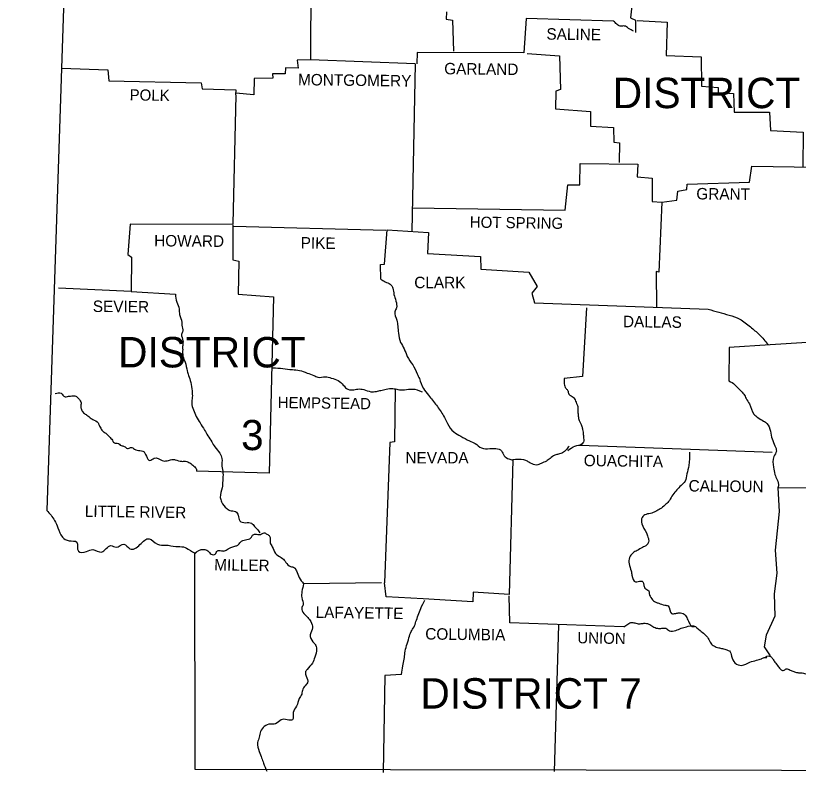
# Model space of a CAD drawing. Extents: x 21307 to 29830, y 1322443 to 1332359.
# Drawn here: x 25205.3 to 25498.6, y 1325967.3 to 1326251 of the extents above; entities that cross this region are included whole.
import ezdxf

# ---------------------------------------------------------------- set-up
doc = ezdxf.new("R2010")
doc.units = 0
doc.layers.add('R_Draft', color=7, linetype='Continuous')

msp = doc.modelspace()

# ---------------------------------------------------------------- linework, layer by layer
at = {"layer": 'R_Draft'}
msp.add_line((25354.96, 1326232.9), (25353.8, 1326170.1), dxfattribs=at)
for points in [[(25205.26, 1326503), (25225.96, 1326336.8), (25216.96, 1326065.5)], [(25370.26, 1326319.9), (25369.86, 1326305.5), (25347.06, 1326305.4), (25344.06, 1326302.8), (25342.36, 1326298.8), (25339.86, 1326299), (25339.76, 1326296.7), (25336.86, 1326296.4), (25336.96, 1326294.3), (25322.46, 1326294.7), (25321.96, 1326293.1), (25315.96, 1326292.9), (25315.76, 1326234.54)], [(25469.16, 1326264.2), (25461.96, 1326265), (25462.26, 1326262.3), (25449.16, 1326261.8), (25448.76, 1326257.9), (25436.46, 1326257.2), (25435.76, 1326250.2), (25437.56, 1326249.3), (25437.56, 1326244.7)], [(25366.76, 1326252.4), (25366.66, 1326249.7), (25368.96, 1326249.3), (25369.36, 1326237.7)], [(25429.36, 1326248.9), (25396.66, 1326249.9), (25395.76, 1326237), (25355.76, 1326237.2), (25355.6, 1326232.87)], [(25438.26, 1326249.2), (25449.46, 1326248.5), (25449.06, 1326236), (25462.16, 1326235.5), (25462.36, 1326224.6), (25468.56, 1326224.1), (25468.56, 1326222.2), (25474.36, 1326221.8), (25474.56, 1326214.8), (25487.76, 1326214.8), (25488.16, 1326207.9), (25500.36, 1326207.3), (25500.26, 1326194.3)], [(25396.96, 1326236.8), (25409.06, 1326235.9), (25409.46, 1326223.3), (25407.76, 1326222.7), (25407.56, 1326216), (25420.66, 1326215.1), (25420.66, 1326209.6), (25429.36, 1326209.1), (25429.46, 1326203.6), (25431.56, 1326203.3), (25431.46, 1326195.9)], [(25315.76, 1326234.54), (25315.76, 1326234.4), (25310.76, 1326234.3), (25311.16, 1326231.3), (25306.36, 1326231.4), (25306.26, 1326229.2), (25301.56, 1326229.2), (25301.66, 1326227.6), (25294.66, 1326227.4), (25294.56, 1326221.3), (25287.77, 1326221.9)], [(25354.96, 1326232.9), (25315.76, 1326234.4)], [(25222.46, 1326231.3), (25239.76, 1326230.7), (25240.16, 1326226.5), (25274.76, 1326225.8), (25275.16, 1326223.6), (25287.76, 1326223.2), (25287.66, 1326221.3)], [(25287.74, 1326221.12), (25286.66, 1326172.9)], [(25353.96, 1326178.9), (25411.16, 1326178.1), (25412.26, 1326187.6), (25416.76, 1326187.6), (25416.86, 1326195.6), (25438.46, 1326195.3), (25438.26, 1326190.5), (25443.86, 1326190.1), (25443.86, 1326181.3), (25447.46, 1326181), (25447.42, 1326180.08)], [(25447.46, 1326181), (25453.06, 1326181.8), (25453.46, 1326185.2), (25456.76, 1326185.8), (25456.96, 1326187.8), (25480.26, 1326188.5), (25481.16, 1326194.6), (25505.06, 1326194.2)], [(25447.46, 1326181), (25446.26, 1326154.8), (25445.36, 1326155.1), (25445.46, 1326141.5)], [(25286.56, 1326172.7), (25248.16, 1326172.8), (25247.26, 1326161.4), (25248.66, 1326160.4), (25248.56, 1326147.6), (25221.26, 1326148.8)], [(25286.66, 1326172.7), (25286.66, 1326159.4), (25288.86, 1326159), (25288.66, 1326146.6), (25301.86, 1326145.6), (25300.26, 1326079.5), (25273.06, 1326080.2)], [(25286.86, 1326172), (25344.06, 1326170.5)], [(25342.16, 1326152.2), (25341.96, 1326157.7), (25343.56, 1326157.8), (25344.56, 1326170.7), (25359.96, 1326169.7), (25359.56, 1326161.8), (25379.46, 1326160.7), (25379.56, 1326155.9), (25397.56, 1326154.8), (25400.66, 1326149.4), (25398.76, 1326147), (25399.66, 1326143.3), (25464.86, 1326140.9)], [(25248.56, 1326147.6), (25265.16, 1326146.6)], [(25419.26, 1326141.4), (25417.76, 1326115.7), (25410.86, 1326114.9)], [(25488.03, 1326127.55), (25472.66, 1326126.6), (25472.56, 1326114.1)], [(25501.86, 1326128.4), (25488.03, 1326127.55)], [(25347.46, 1326111.1), (25347.26, 1326091.2), (25345.46, 1326091), (25343.46, 1326038.3)], [(25416.76, 1326090), (25458.16, 1326088.5), (25488.86, 1326087.3)], [(25391.56, 1326084.4), (25390.26, 1326034), (25376.76, 1326034.9), (25376.66, 1326031.2), (25357.99, 1326032.29)], [(25490.86, 1326074), (25536.06, 1326074.1)], [(25490.86, 1326074), (25491.43, 1326065.09), (25489.96, 1326050.62), (25490.59, 1326042.01), (25489.54, 1326034.25), (25489.75, 1326025.85), (25486.6, 1326018.72), (25485.76, 1326014.31), (25488.07, 1326010.95)], [(25272.26, 1326049.4), (25272.46, 1325968.5), (25638.96, 1325967.9)], [(25342.34, 1326038.29), (25313.16, 1326038)], [(25357.99, 1326032.29), (25344.16, 1326033.1), (25343.46, 1326038.3)], [(25433.16, 1326021.8), (25390.46, 1326023.4), (25390.26, 1326033.5)], [(25408.66, 1326022.5), (25407.06, 1325967.6)], [(25349.86, 1326004), (25343.66, 1326003.6), (25342.96, 1325967.3)]]:
    msp.add_lwpolyline(points, dxfattribs=at)
for points in [[(25436.86, 1326245.2), (25434.96, 1326246.2), (25433.46, 1326247.1), (25431.86, 1326247), (25430.56, 1326247.8), (25429.36, 1326248.9)], [(25342.16, 1326152.2), (25343.76, 1326151.2), (25345.66, 1326150.3), (25346.66, 1326148.8), (25347.06, 1326146.5), (25347.76, 1326144), (25347.96, 1326141.4), (25347.36, 1326140), (25348.16, 1326136.8), (25348.46, 1326134.6), (25348.76, 1326132), (25349.56, 1326128.5), (25350.86, 1326126.1), (25352.06, 1326123.2), (25354.06, 1326120.1), (25355.76, 1326116.7), (25356.56, 1326114.9), (25358.06, 1326111.2), (25359.96, 1326108.7), (25362.96, 1326104.9), (25365.66, 1326101), (25367.16, 1326098.1), (25369.46, 1326094.9), (25372.06, 1326093.3), (25375.36, 1326091.6), (25377.46, 1326090.6), (25379.86, 1326088.9), (25382.96, 1326088.7), (25385.26, 1326088.7), (25387.36, 1326087.8), (25388.36, 1326086), (25390.16, 1326084.8), (25391.56, 1326084.4)], [(25265.16, 1326146.6), (25265.66, 1326143.6), (25266.56, 1326141), (25266.66, 1326139), (25267.56, 1326136), (25267.56, 1326134.9), (25267.86, 1326132.7), (25267.46, 1326131.5), (25267.96, 1326129.1), (25267.86, 1326127.3), (25267.86, 1326125.8), (25267.96, 1326123.3), (25268.76, 1326121.1), (25269.56, 1326117.8), (25270.06, 1326116.1), (25270.86, 1326113.5), (25271.36, 1326110.3), (25271.46, 1326107.9), (25271.26, 1326105.7), (25271.86, 1326103.2), (25272.96, 1326100.7), (25274.36, 1326098.3), (25276.06, 1326095.6), (25277.26, 1326093.5), (25278.76, 1326091.2), (25279.96, 1326089.3), (25281.76, 1326086.9), (25282.56, 1326084.9), (25282.56, 1326082.1), (25282.96, 1326079.5), (25282.86, 1326076.6), (25282.66, 1326074), (25281.96, 1326070.4), (25282.46, 1326068.7), (25284.36, 1326066.2), (25285.56, 1326065.5), (25287.66, 1326065.1), (25288.66, 1326063.7), (25289.26, 1326061.6), (25291.36, 1326060.9), (25293.66, 1326060.7), (25294.76, 1326059.5), (25296.26, 1326057.9), (25296.76, 1326057.1)], [(25464.86, 1326140.9), (25472.66, 1326138.7), (25476.66, 1326137.2), (25480.66, 1326134.3), (25483.96, 1326131.4), (25487.26, 1326127.7)], [(25301.66, 1326119), (25305.46, 1326118.7), (25308.96, 1326118.3), (25311.66, 1326118), (25314.46, 1326117), (25316.96, 1326116.1), (25318.56, 1326115.4), (25321.26, 1326115.6), (25323.56, 1326115.1), (25326.16, 1326114.2), (25328.06, 1326112.5), (25329.26, 1326111.2), (25331.56, 1326110.7), (25333.46, 1326111), (25335.76, 1326110.8), (25338.36, 1326110), (25340.46, 1326110.1), (25342.16, 1326110.5), (25344.16, 1326111), (25346.66, 1326111.2), (25348.56, 1326110.8), (25351.06, 1326110.7), (25353.96, 1326111), (25357.56, 1326110)], [(25410.86, 1326114.9), (25410.86, 1326113), (25411.56, 1326111.2), (25412.26, 1326110.4), (25412.56, 1326109.1), (25413.46, 1326108.5), (25414.76, 1326107.3), (25415.46, 1326105.6), (25415.96, 1326104.5), (25415.96, 1326103.1), (25416.06, 1326101.7), (25416.26, 1326100), (25417.46, 1326097), (25417.76, 1326095.8), (25417.96, 1326094.8), (25418.06, 1326093.1), (25418.06, 1326091.1), (25416.76, 1326090)], [(25472.56, 1326114.1), (25474.86, 1326112.6), (25476.76, 1326110.6), (25478.16, 1326109.1), (25479.06, 1326107.4), (25480.26, 1326105.4), (25481.96, 1326101.6), (25483.46, 1326100.3), (25485.56, 1326099), (25486.86, 1326098.1), (25488.16, 1326095.2), (25488.76, 1326092.3), (25489.86, 1326089.7), (25490.36, 1326087.7), (25489.46, 1326085.7), (25489.26, 1326081.7), (25489.86, 1326079), (25490.66, 1326077), (25491.16, 1326074.7), (25490.86, 1326074)], [(25220.06, 1326109.3), (25222.26, 1326109.4), (25223.76, 1326108.1), (25224.66, 1326108.2), (25226.26, 1326108.4), (25227.76, 1326108.3), (25228.86, 1326107.4), (25229.76, 1326105.8), (25229.66, 1326104.3), (25229.76, 1326103.7), (25230.46, 1326102.4), (25231.66, 1326101.4), (25232.96, 1326100.4), (25234.16, 1326099.6), (25236.16, 1326098.3), (25236.36, 1326097.9), (25237.16, 1326096.3), (25238.16, 1326095), (25239.36, 1326094.2), (25240.66, 1326092.8), (25241.26, 1326092.2), (25242.26, 1326090.8), (25243.36, 1326090.7), (25244.86, 1326089.8), (25245.96, 1326089.5), (25247.16, 1326088.7), (25248.36, 1326089.1), (25249.86, 1326088.5), (25251.86, 1326087.9), (25252.96, 1326087.7), (25254.26, 1326085.8), (25255.56, 1326084.2), (25257.16, 1326085.1), (25260.16, 1326084.2), (25262.06, 1326084.1), (25263.76, 1326084.6), (25265.06, 1326084.5), (25267.46, 1326083.9), (25268.96, 1326083.9), (25270.56, 1326083.3), (25272.06, 1326082.1), (25273.06, 1326080.8), (25273.06, 1326080.2)], [(25412.66, 1326089.5), (25411.56, 1326088.2), (25410.26, 1326087.1), (25408.76, 1326086.6), (25407.36, 1326086.2), (25405.56, 1326085), (25404.16, 1326084), (25402.26, 1326083.1), (25400.46, 1326082.5), (25398.26, 1326083.2), (25397.06, 1326083.9), (25395.76, 1326084.4), (25391.56, 1326084.4)], [(25412.26, 1326087.9), (25414.86, 1326089.6), (25417.76, 1326090)], [(25457.76, 1326087.3), (25457.56, 1326082.3), (25456.86, 1326079.2), (25456.16, 1326076.4), (25454.66, 1326074.8), (25453.06, 1326073.2), (25451.56, 1326071.4), (25450.26, 1326069.2), (25448.96, 1326067.8), (25447.26, 1326066.4), (25445.56, 1326065.4), (25443.66, 1326064.5), (25441.56, 1326064), (25440.06, 1326062.9), (25439.96, 1326060.5), (25441.66, 1326057.1), (25442.26, 1326055.5), (25442.46, 1326053.6), (25441.76, 1326052.5), (25440.16, 1326051.6), (25438.26, 1326050.5), (25436.56, 1326049.5), (25435.36, 1326047.8), (25435.16, 1326045.5), (25435.96, 1326042.8), (25436.26, 1326041.2), (25437.56, 1326038.7), (25438.56, 1326038.8), (25440.36, 1326038.7), (25440.56, 1326038.2), (25440.66, 1326037.7), (25441.06, 1326036.4), (25442.56, 1326035.3), (25442.76, 1326034.3), (25443.66, 1326032.4), (25445.16, 1326031.1), (25446.26, 1326030.7), (25448.56, 1326030), (25449.76, 1326029.7), (25451.06, 1326026.8), (25452.66, 1326026.9), (25453.86, 1326027.1), (25455.86, 1326026.6), (25456.76, 1326025.4), (25457.66, 1326023.4), (25458.86, 1326022), (25459.66, 1326022)], [(25216.96, 1326065.5), (25219.86, 1326061.7), (25221.06, 1326059), (25222.76, 1326055.5), (25225.26, 1326054.1), (25228.16, 1326053.6), (25228.76, 1326050.2), (25231.76, 1326050.1), (25234.16, 1326050.8), (25237.46, 1326049.9), (25240.96, 1326052.3), (25242.96, 1326051.7), (25245.86, 1326052.9), (25248.06, 1326051.1), (25251.86, 1326052.7), (25255.26, 1326054.9), (25258.46, 1326052.8), (25261.56, 1326052.5), (25265.26, 1326052), (25268.16, 1326051.8), (25270.76, 1326050.5), (25272.66, 1326049.2), (25272.26, 1326049.4)], [(25272.26, 1326049.4), (25275.76, 1326050.9), (25277.26, 1326050.4), (25278.56, 1326049.1), (25280.06, 1326049.1), (25280.86, 1326050.3), (25282.36, 1326050.4), (25283.56, 1326050.3), (25284.86, 1326051.1), (25285.96, 1326051.6), (25287.46, 1326052.1), (25288.56, 1326052.5), (25289.56, 1326053.6), (25291.36, 1326054.5), (25293.46, 1326055.2), (25294.06, 1326056.2), (25295.06, 1326056.6), (25297.06, 1326056.5), (25298.36, 1326057.1), (25299.46, 1326056.6), (25300.46, 1326055.9), (25300.66, 1326053.3), (25301.46, 1326051.9), (25302.66, 1326049.4), (25304.36, 1326048.1), (25305.96, 1326046.8), (25306.56, 1326046), (25308.26, 1326044.5), (25309.76, 1326044), (25310.46, 1326042.9), (25311.56, 1326040.3), (25313.16, 1326038)], [(25313.16, 1326038), (25312.56, 1326035.1), (25312.46, 1326032.8), (25312.96, 1326030.1), (25312.46, 1326028.8), (25313.26, 1326026.9), (25314.76, 1326025.4), (25315.86, 1326023.8), (25316.56, 1326021.5), (25315.66, 1326018.9), (25316.66, 1326016.2), (25317.56, 1326015.2), (25318.06, 1326013.6), (25317.36, 1326010.5), (25316.46, 1326008.2), (25314.46, 1326005.9), (25313.86, 1326004.8), (25314.16, 1326003.3), (25314.66, 1326000.9), (25314.16, 1326000.2), (25312.86, 1325998.5), (25312.46, 1325996.6), (25311.56, 1325995), (25310.56, 1325992.1), (25309.26, 1325989.7), (25309.06, 1325987), (25307.06, 1325987), (25304.76, 1325987), (25302.66, 1325985.5), (25300.76, 1325985.4), (25298.46, 1325984.5), (25297.06, 1325982.6), (25296.56, 1325980.5), (25295.96, 1325978.5), (25296.56, 1325975.1), (25297.46, 1325972.7), (25298.16, 1325970.8), (25299.36, 1325967.7)], [(25349.86, 1326004), (25350.36, 1326007.2), (25350.86, 1326009.7), (25351.16, 1326012.1), (25351.76, 1326014.8), (25352.66, 1326017.7), (25353.46, 1326020.1), (25354.56, 1326021.8), (25355.26, 1326023.8), (25356.16, 1326026.2), (25357.06, 1326028.7), (25358.66, 1326031.9)], [(25433.16, 1326021.8), (25434.76, 1326022.9), (25436.26, 1326023.5), (25437.76, 1326023.2), (25439.36, 1326023), (25440.76, 1326023.2), (25442.56, 1326022.9), (25444.06, 1326022), (25445.76, 1326021.3), (25447.46, 1326021.3), (25448.96, 1326021.3), (25450.26, 1326020.4), (25452.66, 1326020.5), (25454.66, 1326021.3), (25456.66, 1326021.9), (25459.36, 1326022.2), (25461.76, 1326020.5), (25463.46, 1326019.1), (25464.86, 1326017.5), (25465.86, 1326015.7), (25466.96, 1326014.7), (25468.76, 1326014), (25470.16, 1326013.7), (25471.86, 1326013.2), (25472.76, 1326012.8), (25473.56, 1326010.9), (25474.86, 1326008.3), (25477.36, 1326007.4), (25480.46, 1326008.6), (25482.96, 1326009.3), (25484.76, 1326009.9), (25485.86, 1326010.3), (25486.86, 1326010.4), (25486.56, 1326010.6), (25487.76, 1326010.9), (25488.86, 1326010.1), (25489.56, 1326009), (25490.76, 1326007.4), (25491.86, 1326006), (25492.96, 1326005.5), (25494.06, 1326006.1), (25495.56, 1326005.6), (25496.86, 1326005.1), (25498.36, 1326004.7), (25499.66, 1326004.6), (25501.36, 1326004.2), (25502.66, 1326003.5), (25503.86, 1326002.8), (25505.06, 1326001.5), (25506.26, 1325999.5), (25506.66, 1325997.9), (25508.06, 1325996.3), (25509.36, 1325996.3), (25511.26, 1325993.7), (25511.96, 1325992.7), (25513.46, 1325990.9), (25514.56, 1325990.9), (25516.66, 1325990.5)]]:
    msp.add_spline(points, degree=3, dxfattribs=at)

# ---------------------------------------------------------------- texts
for s, height, rotation, p in [('SALINE', 4.301, 359.1491, (25404.16, 1326242)), ('GARLAND', 4.301, 359.3658, (25365.86, 1326229)), ('MONTGOMERY', 4.301, 359.2944, (25311.06, 1326224.9)), ('POLK', 4.199, 359.2152, (25247.96, 1326219.2)), ('GRANT', 4.301, 359.4032, (25460.36, 1326182.1)), ('HOT SPRING', 4.201, 359.2216, (25375.46, 1326171.5)), ('HOWARD', 4.301, 359.5145, (25257.16, 1326164.5)), ('PIKE', 4.299, 359.0452, (25312.06, 1326163.7)), ('SEVIER', 4.301, 359.4271, (25234.16, 1326139.9)), ('DALLAS', 4.3, 359.2462, (25432.86, 1326134.2)), ('HEMPSTEAD', 4.199, 359.1885, (25303.46, 1326103.9)), ('OUACHITA', 4.301, 359.2043, (25418.16, 1326082.1)), ('CALHOUN', 4.301, 359.3634, (25457.46, 1326072.6)), ('LITTLE RIVER', 4.3007, 359.1697, (25231.16, 1326063.1)), ('MILLER', 4.3, 359.1319, (25279.66, 1326043)), ('LAFAYETTE', 4.299, 359.1839, (25317.66, 1326025.2)), ('COLUMBIA', 4.3, 359.2125, (25358.76, 1326017.1)), ('UNION', 4.201, 358.9584, (25415.76, 1326015.7))]:
    msp.add_text(s, height=height, rotation=rotation, dxfattribs=at).set_placement(p)
for s, height, p in [('DISTRICT 6', 11.4, (25429.06, 1326216.3)), ('CLARK', 4.3, (25354.66, 1326148.8)), ('DISTRICT', 11.4, (25243.66, 1326119.1)), ('3', 11.3, (25289.76, 1326088.1)), ('NEVADA', 4.3, (25351.36, 1326083.1)), ('DISTRICT 7', 11.4, (25356.96, 1325991.2))]:
    msp.add_text(s, height=height, dxfattribs=at).set_placement(p)

doc.saveas('drawing.dxf')
